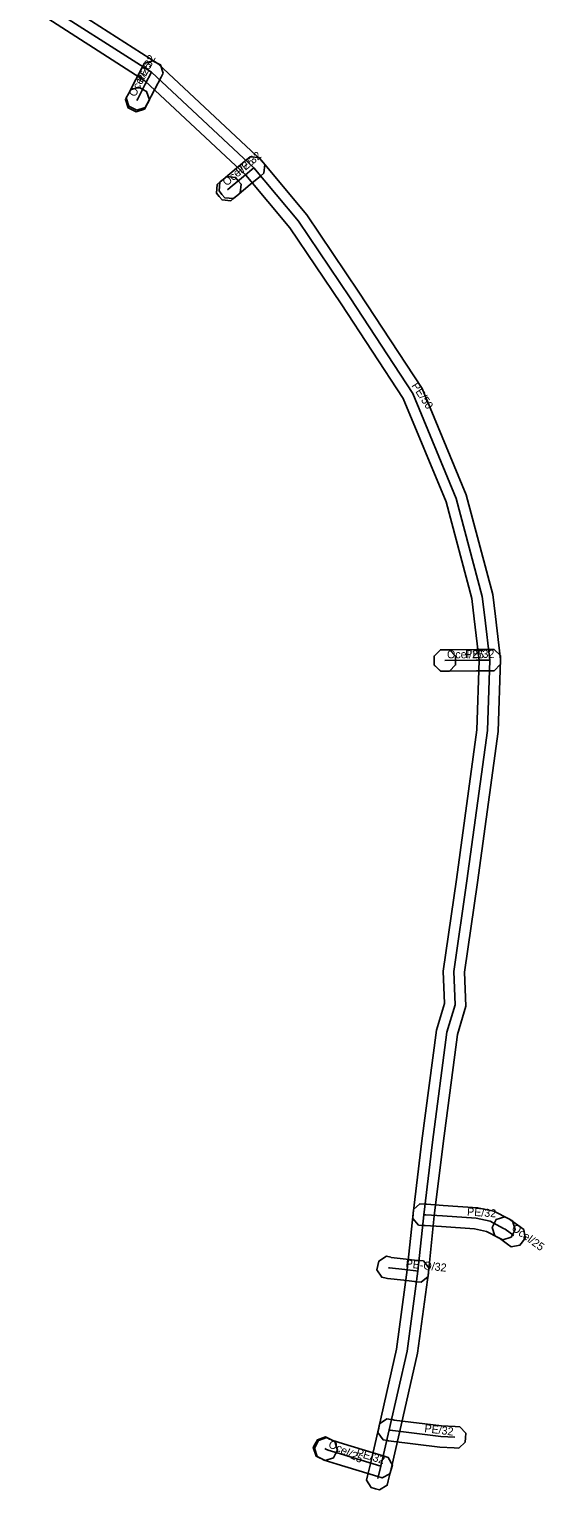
# Model space of a CAD drawing. Extents: x -678368 to -678136, y -1057358 to -1057053.
# Drawn here: x -678198.4 to -678150.1, y -1057358 to -1057221.1 of the extents above; entities that cross this region are included whole.
import ezdxf

# ---------------------------------------------------------------- set-up
doc = ezdxf.new("R2010")
doc.units = 0
for name, color, linetype in [('1', 7, 'Continuous'), ('24', 7, 'Continuous'), ('30', 7, 'Continuous')]:
    doc.layers.add(name, color=color, linetype=linetype)

msp = doc.modelspace()

# ---------------------------------------------------------------- linework, layer by layer
at = {"layer": '1'}
msp.add_lwpolyline([(-678197.31, -1057217.28), (-678186.36, -1057224.3), (-678176.68, -1057233.36), (-678172.43, -1057238.46), (-678167.55, -1057245.7), (-678161.62, -1057254.73), (-678157.49, -1057264.72), (-678155.01, -1057274.04), (-678154.76, -1057276.1), (-678154.29, -1057280.15), (-678154.5, -1057286.89), (-678156.44, -1057301.04), (-678157.65, -1057309.45), (-678157.52, -1057312.65), (-678158.33, -1057315.3), (-678159.67, -1057325.52), (-678160.49, -1057332.31), (-678161.04, -1057337.6), (-678162.05, -1057345.16), (-678163.74, -1057352.6), (-678164.52, -1057356.01), (-678164.8, -1057357.15), (-678164.9, -1057357.55), (-678165.61, -1057357.98), (-678166.01, -1057357.88), (-678166.41, -1057357.78), (-678166.84, -1057357.07), (-678166.74, -1057356.67), (-678166.46, -1057355.55), (-678165.69, -1057352.15), (-678164.02, -1057344.8), (-678163.02, -1057337.36), (-678162.48, -1057332.08), (-678161.65, -1057325.27), (-678160.29, -1057314.88), (-678159.54, -1057312.39), (-678159.65, -1057309.35), (-678158.42, -1057300.76), (-678156.5, -1057286.73), (-678156.29, -1057280.23), (-678156.75, -1057276.33), (-678156.97, -1057274.42), (-678159.39, -1057265.36), (-678163.4, -1057255.67), (-678169.21, -1057246.8), (-678174.03, -1057239.66), (-678178.14, -1057234.74), (-678187.6, -1057225.88), (-678198.45, -1057218.92)], dxfattribs=at)
for points in [[(-678185.9, -1057225.18), (-678186.09, -1057225.55), (-678186.68, -1057226.68), (-678187.39, -1057228.04), (-678187.58, -1057228.4), (-678188.37, -1057228.65), (-678188.73, -1057228.46), (-678189.1, -1057228.27), (-678189.35, -1057227.48), (-678189.16, -1057227.11), (-678188.45, -1057225.76), (-678187.87, -1057224.63), (-678187.68, -1057224.26), (-678186.89, -1057224.01), (-678186.52, -1057224.2), (-678186.15, -1057224.39)], [(-678187.19, -1057227.67), (-678187.38, -1057228.03), (-678187.46, -1057228.19), (-678187.65, -1057228.55), (-678188.44, -1057228.81), (-678188.81, -1057228.62), (-678189.18, -1057228.43), (-678189.43, -1057227.64), (-678189.24, -1057227.27), (-678189.16, -1057227.11), (-678188.97, -1057226.75), (-678188.18, -1057226.5), (-678187.81, -1057226.69), (-678187.45, -1057226.88)], [(-678176.45, -1057234.55), (-678176.77, -1057234.82), (-678177.73, -1057235.62), (-678178.98, -1057236.66), (-678179.3, -1057236.93), (-678180.13, -1057236.85), (-678180.39, -1057236.54), (-678180.66, -1057236.22), (-678180.58, -1057235.39), (-678180.27, -1057235.13), (-678179.01, -1057234.08), (-678178.05, -1057233.28), (-678177.73, -1057233.02), (-678176.91, -1057233.09), (-678176.64, -1057233.41), (-678176.38, -1057233.73)], [(-678178.67, -1057236.4), (-678178.98, -1057236.66), (-678179.23, -1057236.87), (-678179.55, -1057237.13), (-678180.37, -1057237.06), (-678180.64, -1057236.74), (-678180.9, -1057236.42), (-678180.83, -1057235.6), (-678180.51, -1057235.33), (-678180.27, -1057235.13), (-678179.95, -1057234.86), (-678179.12, -1057234.94), (-678178.86, -1057235.26), (-678178.59, -1057235.57)], [(-678159.08, -1057281.23), (-678159.49, -1057281.23), (-678159.51, -1057281.23), (-678159.92, -1057281.23), (-678160.51, -1057280.65), (-678160.51, -1057280.23), (-678160.51, -1057279.82), (-678159.92, -1057279.23), (-678159.51, -1057279.23), (-678159.49, -1057279.23), (-678159.08, -1057279.23), (-678158.49, -1057279.82), (-678158.49, -1057280.23), (-678158.49, -1057280.65)], [(-678154.87, -1057281.19), (-678155.28, -1057281.19), (-678156.55, -1057281.2), (-678159.48, -1057281.23), (-678159.89, -1057281.24), (-678160.49, -1057280.66), (-678160.49, -1057280.24), (-678160.49, -1057279.83), (-678159.91, -1057279.24), (-678159.5, -1057279.23), (-678156.57, -1057279.2), (-678155.3, -1057279.19), (-678154.89, -1057279.19), (-678154.29, -1057279.77), (-678154.29, -1057280.18), (-678154.29, -1057280.59)], [(-678161.83, -1057331.17), (-678161.41, -1057331.2), (-678161.2, -1057331.21), (-678159.67, -1057331.32), (-678156.44, -1057331.54), (-678154.92, -1057331.86), (-678153.52, -1057332.59), (-678153.16, -1057332.78), (-678152.91, -1057333.57), (-678153.1, -1057333.94), (-678153.3, -1057334.31), (-678154.08, -1057334.55), (-678154.45, -1057334.36), (-678155.6, -1057333.76), (-678156.72, -1057333.52), (-678159.8, -1057333.31), (-678161.34, -1057333.21), (-678161.55, -1057333.19), (-678161.97, -1057333.16), (-678162.51, -1057332.54), (-678162.48, -1057332.12), (-678162.45, -1057331.71)], [(-678153.89, -1057332.4), (-678153.52, -1057332.59), (-678153.32, -1057332.7), (-678152.45, -1057333.33), (-678152.11, -1057333.58), (-678151.98, -1057334.39), (-678152.23, -1057334.73), (-678152.47, -1057335.06), (-678153.29, -1057335.19), (-678153.63, -1057334.95), (-678154.38, -1057334.4), (-678154.46, -1057334.36), (-678154.82, -1057334.17), (-678155.07, -1057333.38), (-678154.87, -1057333.01), (-678154.68, -1057332.64)], [(-678161.72, -1057338.52), (-678162.14, -1057338.48), (-678162.33, -1057338.45), (-678163.35, -1057338.33), (-678164.86, -1057338.17), (-678165.01, -1057338.14), (-678165.41, -1057338.05), (-678165.86, -1057337.35), (-678165.77, -1057336.94), (-678165.68, -1057336.54), (-678164.98, -1057336.09), (-678164.57, -1057336.18), (-678164.54, -1057336.19), (-678163.13, -1057336.35), (-678162.11, -1057336.47), (-678161.93, -1057336.49), (-678161.51, -1057336.53), (-678160.99, -1057337.17), (-678161.04, -1057337.58), (-678161.08, -1057338)], [(-678158.2, -1057354.07), (-678158.62, -1057354.05), (-678159.96, -1057353.99), (-678164.54, -1057353.42), (-678164.79, -1057353.38), (-678164.88, -1057353.36), (-678165.29, -1057353.29), (-678165.77, -1057352.61), (-678165.7, -1057352.21), (-678165.63, -1057351.8), (-678164.95, -1057351.32), (-678164.55, -1057351.39), (-678164.45, -1057351.4), (-678164.24, -1057351.44), (-678159.8, -1057351.99), (-678158.52, -1057352.05), (-678158.11, -1057352.07), (-678157.55, -1057352.68), (-678157.57, -1057353.1), (-678157.59, -1057353.51)], [(-678170.72, -1057355.24), (-678171.09, -1057355.06), (-678171.2, -1057355), (-678171.57, -1057354.82), (-678171.83, -1057354.03), (-678171.64, -1057353.66), (-678171.45, -1057353.29), (-678170.67, -1057353.03), (-678170.3, -1057353.22), (-678170.19, -1057353.27), (-678169.82, -1057353.46), (-678169.56, -1057354.25), (-678169.75, -1057354.61), (-678169.93, -1057354.99)], [(-678170.56, -1057353.08), (-678170.19, -1057353.27), (-678170.08, -1057353.33), (-678169, -1057353.66), (-678165.2, -1057354.82), (-678164.8, -1057354.95), (-678164.41, -1057355.68), (-678164.53, -1057356.07), (-678164.66, -1057356.47), (-678165.39, -1057356.86), (-678165.78, -1057356.74), (-678169.58, -1057355.57), (-678170.82, -1057355.19), (-678171.09, -1057355.06), (-678171.46, -1057354.87), (-678171.72, -1057354.09), (-678171.53, -1057353.72), (-678171.35, -1057353.35)]]:
    msp.add_lwpolyline(points, close=True, dxfattribs=at)
at = {"layer": '24'}
for points in [[(-678197.88, -1057218.1), (-678186.98, -1057225.09), (-678177.41, -1057234.05), (-678173.23, -1057239.06), (-678168.38, -1057246.25), (-678162.51, -1057255.2), (-678158.44, -1057265.04), (-678155.99, -1057274.23), (-678155.76, -1057276.22), (-678155.29, -1057280.19), (-678155.5, -1057286.81), (-678157.43, -1057300.9), (-678158.65, -1057309.4), (-678158.53, -1057312.52), (-678159.31, -1057315.09), (-678160.66, -1057325.39), (-678161.48, -1057332.2), (-678162.03, -1057337.48), (-678163.03, -1057344.98), (-678164.71, -1057352.37), (-678165.49, -1057355.78), (-678165.77, -1057356.91)], [(-678186.98, -1057225.09), (-678187.57, -1057226.22), (-678188.27, -1057227.57)], [(-678188.27, -1057227.57), (-678188.35, -1057227.73)], [(-678177.41, -1057234.05), (-678178.37, -1057234.85), (-678179.62, -1057235.9)], [(-678179.62, -1057235.9), (-678179.87, -1057236.1)], [(-678159.49, -1057280.23), (-678159.51, -1057280.23)], [(-678155.29, -1057280.19), (-678156.56, -1057280.2), (-678159.49, -1057280.23)], [(-678161.48, -1057332.2), (-678161.27, -1057332.21), (-678159.73, -1057332.31), (-678156.58, -1057332.53), (-678155.26, -1057332.81), (-678153.99, -1057333.48)], [(-678153.99, -1057333.48), (-678153.85, -1057333.55), (-678153.04, -1057334.14)], [(-678162.03, -1057337.48), (-678162.22, -1057337.46), (-678163.24, -1057337.34), (-678164.7, -1057337.18), (-678164.79, -1057337.16)], [(-678158.57, -1057353.05), (-678159.88, -1057352.99), (-678164.39, -1057352.43), (-678164.62, -1057352.39), (-678164.71, -1057352.37)], [(-678170.64, -1057354.17), (-678170.75, -1057354.11)], [(-678170.64, -1057354.17), (-678170.45, -1057354.26), (-678169.29, -1057354.61), (-678165.49, -1057355.78)]]:
    msp.add_lwpolyline(points, dxfattribs=at)

# ---------------------------------------------------------------- texts
at = {"layer": '30'}
for s, rotation, p in [('PE/32', 62.5109, (-678187.83, -1057226.13)), ('Ocel/25', 62.6909, (-678188.51, -1057227.45)), ('Ocel/25', 39.8056, (-678179.95, -1057235.8)), ('PE/32', 39.7966, (-678178.72, -1057234.77)), ('PE/50', 303.2595, (-678162.66, -1057254.47)), ('Ocel/25', 360, (-678159.3, -1057280.03)), ('PE/32', 0.5661, (-678157.59, -1057280.01)), ('PE/32', 356.0991, (-678157.44, -1057332.26)), ('Ocel/25', 323.9517, (-678153.31, -1057333.6)), ('PE-O/32', 353.746, (-678163.21, -1057337.12)), ('PE/32', 352.9219, (-678161.45, -1057352.57)), ('Ocel/25', 333.2251, (-678170.49, -1057353.94)), ('PE/32', 342.9598, (-678167.87, -1057354.79))]:
    msp.add_text(s, height=0.75, rotation=rotation, dxfattribs=at).set_placement(p)

doc.saveas('drawing.dxf')
